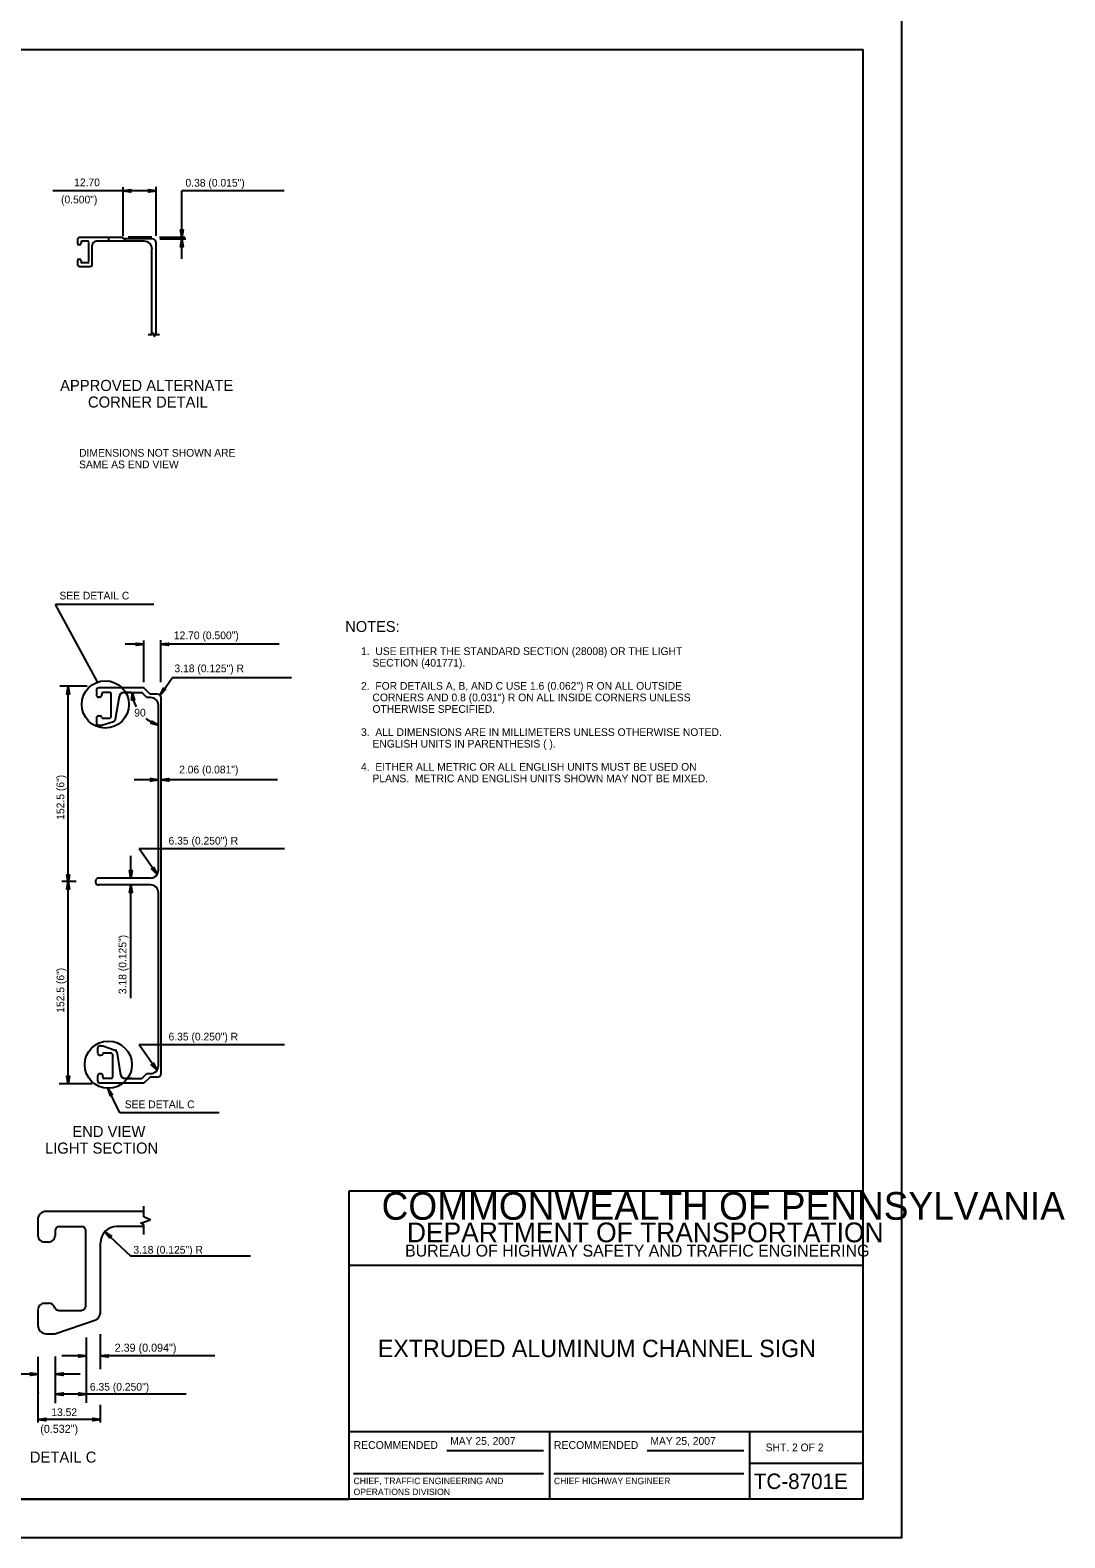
# Model space of a CAD drawing. Extents: x 647822 to 648727, y 298458 to 299646.
# Drawn here: x 648324 to 648727, y 298458 to 299044 of the extents above; entities that cross this region are included whole.
import ezdxf

# ---------------------------------------------------------------- set-up
doc = ezdxf.new("R2010")
doc.units = 0
for name, color, linetype in [('1', 7, 'Continuous'), ('2', 7, 'Continuous'), ('3', 7, 'Continuous'), ('XCS-GRID-MIN', 7, 'Continuous')]:
    doc.layers.add(name, color=color, linetype=linetype)

# ---------------------------------------------------------------- blocks, each defined once
blk = doc.blocks.new('RARROW')
at = {"layer": '3'}
blk.add_lwpolyline([(-2.2695, 0.285), (-2.184875, 0.12075), (0, 0), (-2.2695, 0.285), (-2.38575, 0.384625), (0, 0), (-2.183125, -0.108), (-2.262875, -0.2705), (0, 0), (-2.38575, -0.379125), (-2.262875, -0.2705)], dxfattribs=at)

msp = doc.modelspace()

# ---------------------------------------------------------------- linework, layer by layer
at = {"layer": '1'}
for p, q in [((647862.31, 299036.63), (648648.31, 299036.63)), ((648648.31, 298472.63), (648648.31, 299036.63)), ((648448.31, 298472.63), (648448.31, 298592.63)), ((648448.31, 298592.63), (648648.31, 298592.63)), ((648648.31, 298563.63), (648448.31, 298563.63)), ((648448.31, 298499), (648648.31, 298499)), ((648526.31, 298499), (648526.31, 298472.63)), ((648604.19, 298472.63), (648604.19, 298499)), ((648486.24, 298491.57), (648523.87, 298491.57)), ((648564.24, 298491.57), (648601.87, 298491.57)), ((648449.99, 298482.68), (648523.87, 298482.68)), ((648527.99, 298482.68), (648601.87, 298482.68)), ((648604.19, 298486.63), (648648.31, 298486.63)), ((648648.31, 298472.63), (647862.31, 298472.63)), ((647862.31, 298472.63), (648448.31, 298472.63))]:
    msp.add_line(p, q, dxfattribs=at)
at = {"layer": '2'}
for p, q in [((648373.15, 298981.61), (648332.95, 298981.61)), ((648360.27, 298964.08), (648360.27, 298982.99)), ((648373.15, 298964.08), (648373.15, 298983.24)), ((648422.96, 298981.61), (648383.15, 298981.61)), ((648383.15, 298963.45), (648383.15, 298981.61)), ((648342.52, 298962.58), (648342.52, 298961.2)), ((648360.27, 298963.45), (648343.27, 298963.45)), ((648354.65, 298963.45), (648354.65, 298962.08)), ((648360.27, 298962.95), (648360.27, 298963.45)), ((648371.65, 298962.95), (648360.27, 298962.95)), ((648361.02, 298962.08), (648361.02, 298962.95)), ((648371.52, 298963.58), (648362.27, 298963.58)), ((648384.4, 298963.45), (648374.4, 298963.45)), ((648384.65, 298962.83), (648374.52, 298962.83)), ((648383.15, 298955.2), (648383.15, 298962.83)), ((648343.27, 298960.58), (648343.15, 298960.58)), ((648343.9, 298961.58), (648343.9, 298961.2)), ((648346.52, 298962.08), (648344.27, 298962.08)), ((648346.9, 298954.08), (648346.9, 298961.58)), ((648348.27, 298953.08), (648348.27, 298960.45)), ((648368.52, 298962.08), (648349.9, 298962.08)), ((648371.52, 298925.7), (648371.52, 298958.95)), ((648373.15, 298925.7), (648373.15, 298961.45)), ((648342.52, 298954.45), (648342.52, 298953.08)), ((648343.15, 298955.08), (648343.27, 298955.08)), ((648343.27, 298952.2), (648347.52, 298952.2)), ((648343.9, 298954.45), (648343.9, 298954.08)), ((648344.27, 298953.7), (648346.52, 298953.7)), ((648370.02, 298925.7), (648371.77, 298925.7)), ((648372.9, 298925.7), (648374.4, 298925.7)), ((648372.22, 298820.73), (648333.97, 298820.73)), ((648350.25, 298790.63), (648333.97, 298820.73)), ((648368.38, 298805.22), (648361.12, 298805.22)), ((648368.38, 298790.5), (648368.38, 298806.72)), ((648375, 298790.5), (648375, 298806.85)), ((648420.97, 298805.22), (648375, 298805.22)), ((648346.25, 298788.88), (648335.62, 298788.88)), ((648338.88, 298712.5), (648338.88, 298788.88)), ((648349.88, 298787.25), (648349.88, 298785.38)), ((648368.38, 298788.25), (648350.88, 298788.25)), ((648370.75, 298785.88), (648368.38, 298788.25)), ((648374.65, 298785.41), (648379.38, 298792.13)), ((648425.82, 298792.13), (648379.38, 298792.13)), ((648351.25, 298784.63), (648350.62, 298784.63)), ((648352, 298786), (648352, 298785.38)), ((648355.12, 298786.5), (648352.5, 298786.5)), ((648355.62, 298777), (648355.62, 298786)), ((648357.38, 298776.13), (648358.88, 298785)), ((648363.38, 298786.5), (648360.5, 298786.5)), ((648360.62, 298786.5), (648367.62, 298786.5)), ((648369.5, 298784.5), (648367.62, 298786.5)), ((648371, 298784.5), (648369.5, 298784.5)), ((648373.53, 298785.88), (648370.75, 298785.88)), ((648374, 298717.38), (648374, 298781.5)), ((648375.12, 298638.38), (648375.12, 298784.28)), ((648349.88, 298776.63), (648349.88, 298774.75)), ((648350.62, 298777.38), (648351.25, 298777.38)), ((648352, 298773.75), (648356.88, 298775.38)), ((648352.38, 298776.5), (648355.12, 298776.5)), ((648350.88, 298773.75), (648352, 298773.75)), ((648374, 298752.5), (648364.62, 298752.5)), ((648420.35, 298752.5), (648375.12, 298752.5)), ((648363.25, 298714.25), (648363.25, 298722.88)), ((648373.5, 298715.63), (648366.5, 298725.63)), ((648423.15, 298725.63), (648366.5, 298725.63)), ((648342, 298713), (648336.38, 298713)), ((648338.88, 298634.25), (648338.88, 298713)), ((648371, 298711.63), (648350.75, 298711.63)), ((648371, 298714.25), (648350.88, 298714.25)), ((648363.25, 298667.5), (648363.25, 298711.63)), ((648374, 298641.13), (648374, 298708.5)), ((648350.38, 298646.25), (648350.38, 298648)), ((648351.38, 298649), (648352.38, 298649)), ((648352.38, 298649), (648357.25, 298647.38)), ((648352.88, 298646.25), (648355.62, 298646.25)), ((648357.88, 298646.63), (648359.25, 298637.75)), ((648373.38, 298639.5), (648366.5, 298649.38)), ((648423.15, 298649.38), (648366.5, 298649.38)), ((648351.12, 298645.38), (648351.62, 298645.38)), ((648356.12, 298645.75), (648356.12, 298636.88)), ((648348.25, 298634.25), (648335.38, 298634.25)), ((648350.38, 298635.5), (648350.38, 298637.38)), ((648351.62, 298638.13), (648351.12, 298638.13)), ((648368.38, 298634.5), (648351.38, 298634.5)), ((648352.38, 298636.88), (648352.38, 298637.38)), ((648355.62, 298636.25), (648352.88, 298636.25)), ((648363.75, 298636.25), (648361, 298636.25)), ((648361.12, 298636.25), (648367.62, 298636.25)), ((648367.62, 298636.25), (648369.5, 298638.25)), ((648370.75, 298636.88), (648368.38, 298634.5)), ((648369.5, 298638.25), (648371, 298638.25)), ((648373.5, 298636.88), (648370.75, 298636.88)), ((648359, 298623), (648354.38, 298632.5)), ((648397.61, 298623), (648359, 298623)), ((648327.08, 298581.43), (648327.08, 298575.25)), ((648368.21, 298584.63), (648330.28, 298584.63)), ((648368.33, 298582.5), (648368.33, 298586.63)), ((648333.78, 298577.03), (648333.78, 298575.28)), ((648335.34, 298578.75), (648344.13, 298578.75)), ((648345.83, 298547.75), (648345.83, 298577.05)), ((648353.18, 298576.72), (648363.25, 298567.17)), ((648368.33, 298578.75), (648357.86, 298578.75)), ((648368.33, 298575.63), (648368.33, 298579.38)), ((648331.31, 298572.67), (648329.56, 298572.67)), ((648351.46, 298544.88), (648351.46, 298572.35)), ((648409.83, 298567.17), (648363.25, 298567.17)), ((648327.08, 298546.25), (648327.08, 298540.38)), ((648329.46, 298548.88), (648331.33, 298548.88)), ((648335.21, 298546.13), (648344.21, 298546.13)), ((648333.71, 298537), (648349.71, 298542.38)), ((648330.33, 298537), (648333.71, 298537)), ((648346.08, 298510.16), (648346.08, 298535.5)), ((648351.46, 298523.28), (648351.46, 298536.88)), ((648327.21, 298502.53), (648327.21, 298528.04)), ((648333.96, 298510.03), (648333.96, 298528.16)), ((648346.08, 298528.38), (648336.46, 298528.38)), ((648345.71, 298528.38), (648340.5, 298528.38)), ((648395.97, 298528.38), (648351.33, 298528.38)), ((648365.08, 298528.38), (648351.46, 298528.38)), ((648327.21, 298521.29), (648297.29, 298521.29)), ((648343.55, 298521.29), (648333.96, 298521.29)), ((648338.35, 298521.29), (648333.96, 298521.29)), ((648327.21, 298515), (648327.08, 298515)), ((648327.21, 298514.22), (648327.21, 298514.09)), ((648384.77, 298513.52), (648333.96, 298513.52)), ((648351.46, 298502.53), (648351.46, 298509.41)), ((648351.46, 298503.63), (648327.21, 298503.63))]:
    msp.add_line(p, q, dxfattribs=at)
for points in [[(648371.77, 298925.7), (648372.02, 298926.2), (648372.52, 298924.95), (648372.9, 298925.7)], [(648368.33, 298579.38), (648367.21, 298580), (648370.83, 298581.38), (648368.33, 298582.5)]]:
    msp.add_lwpolyline(points, dxfattribs=at)
for centre in [(648353.36, 298781.82), (648354.51, 298641.68)]:
    msp.add_circle(centre, 9.19, dxfattribs=at)
for centre, radius, start, end in [((648343.29, 298962.61), 0.795, 90, 180), ((648371.56, 298961.3), 1.6, 0, 90), ((648343.11, 298961.22), 0.612, 180, 270), ((648343.29, 298961.22), 0.612, 270, 0), ((648344.3, 298961.62), 0.398, 90, 180), ((648346.49, 298961.62), 0.398, 0, 90), ((648349.87, 298960.42), 1.59, 90, 180), ((648368.49, 298958.95), 3.08, 0, 90), ((648343.11, 298954.43), 0.612, 90, 180), ((648343.29, 298953.05), 0.795, 180, 270), ((648343.29, 298954.43), 0.612, 0, 90), ((648344.3, 298954.04), 0.398, 180, 270), ((648346.49, 298954.04), 0.398, 270, 0), ((648347.49, 298953.05), 0.795, 270, 0), ((648375.21, 298786.75), 11.37, 181.27007, 209.92369), ((648371, 298781.5), 3, 0, 90), ((648373.53, 298784.28), 1.6, 0, 90), ((648378.03, 298787.43), 14.21, 231.28314, 253.53268), ((648370.95, 298717.33), 3.08, 270, 0), ((648350.82, 298712.94), 1.31, 91.68468, 272.80637), ((648370.97, 298708.56), 3.08, 0, 90), ((648370.97, 298641.28), 3.08, 270, 0), ((648373.45, 298638.41), 1.6, 270, 0), ((648330.28, 298581.43), 3.2, 90, 180), ((648344.13, 298577.05), 1.7, 0, 90), ((648357.86, 298572.35), 6.4, 90, 180)]:
    msp.add_arc(centre, radius, start, end, dxfattribs=at)
for centre, major_axis, start_param, end_param in [((648350.89, 298787.24), (0, -1.04), 3.141593, 4.712389), ((648350.66, 298785.43), (0, -0.797), 4.712389, 6.283185), ((648351.2, 298785.44), (0, 0.797), 3.141593, 4.712389), ((648352.44, 298785.95), (0, -0.518), 3.141593, 4.712389), ((648355.13, 298785.95), (0, 0.518), 4.712389, 6.283185), ((648360.67, 298784.44), (0, -2.07), 3.141593, 4.712389), ((648350.66, 298776.58), (0, 0.797), 0, 1.570796), ((648351.2, 298776.59), (0, 0.797), 5.030839, 6.283185), ((648352.37, 298777.06), (0, -0.518), 5.099486, 6.283185), ((648355.13, 298777.06), (0, 0.518), 3.141593, 4.712389), ((648356.37, 298776.3), (0, -1.04), 0.462932, 1.480604), ((648350.89, 298774.78), (0, -1.04), 4.712389, 6.283185), ((648351.35, 298648.01), (0, -1.04), 3.141593, 4.712389), ((648351.12, 298646.2), (0, -0.797), 4.712389, 6.283185), ((648351.67, 298646.19), (0, -0.797), 0, 1.252346), ((648352.84, 298645.73), (0, 0.518), 0, 1.183699), ((648355.6, 298645.73), (0, 0.518), 4.712389, 6.283185), ((648356.83, 298646.49), (0, 1.04), 4.802582, 5.820253), ((648351.12, 298637.35), (0, -0.797), 3.141593, 4.712389), ((648351.35, 298635.54), (0, -1.04), 4.712389, 6.283185), ((648351.67, 298637.34), (0, 0.797), 4.712389, 6.283185), ((648352.91, 298636.83), (0, -0.518), 4.712389, 6.283185), ((648355.6, 298636.83), (0, -0.518), 0, 1.570796), ((648361.14, 298638.34), (0, -2.07), 4.712389, 6.283185), ((648335.38, 298577.03), (0, -1.7), 3.141593, 4.712389), ((648329.56, 298575.28), (0, -2.61), 4.712389, 6.283185), ((648331.31, 298575.28), (0, 2.61), 3.141593, 4.712389), ((648329.56, 298546.3), (0, 2.61), 0, 1.570796), ((648331.33, 298546.33), (0, 2.61), 5.030839, 6.283185), ((648335.17, 298547.86), (0, -1.7), 5.099486, 6.283185), ((648344.2, 298547.86), (0, 1.7), 3.141593, 4.712389), ((648330.3, 298540.39), (0, -3.39), 4.712389, 6.283185), ((648348.24, 298545.37), (0, -3.39), 0.462932, 1.480604)]:
    msp.add_ellipse(centre, major_axis=major_axis, ratio=0.943396, start_param=start_param, end_param=end_param, dxfattribs=at)
at = {"layer": 'XCS-GRID-MIN'}
msp.add_lwpolyline([(647822.31, 299051.63), (648663.31, 299051.63), (648663.31, 298457.63), (647822.31, 298457.63)], close=True, dxfattribs=at)

# ---------------------------------------------------------------- block references
at = {"layer": '2'}
for p, xscale, yscale, rotation in [((648360.27, 298981.61), 1.2574347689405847, 1.3092961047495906, 180), ((648383.15, 298962.83), 1.2574347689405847, 1.3092961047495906, 89.99999999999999), ((648383.15, 298963.45), 1.2574347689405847, 1.3092961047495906, -90.00000000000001), ((648375, 298805.22), 1.2574347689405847, 1.3092961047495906, 180), ((648338.88, 298788.88), 1.2574347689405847, 1.3092961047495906, 89.99999999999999), ((648363.84, 298786.5), 1.257434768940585, 1.3092961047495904, 97.46813373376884), ((648374.65, 298785.41), 1.257434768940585, 1.3092961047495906, -124.96513947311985), ((648374, 298773.8), 1.2574347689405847, 1.3092961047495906, -21.75660693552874), ((648375.12, 298752.5), 1.2574347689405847, 1.3092961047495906, 180), ((648363.25, 298714.25), 1.2574347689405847, 1.3092961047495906, -90.00000000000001), ((648373.5, 298715.63), 1.2574347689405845, 1.3092961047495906, -55.40907217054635), ((648338.88, 298713), 1.2574347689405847, 1.3092961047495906, 89.99999999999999), ((648338.88, 298712.5), 1.2574347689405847, 1.3092961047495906, -90.00000000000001), ((648363.25, 298711.63), 1.2574347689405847, 1.3092961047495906, 89.99999999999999), ((648373.38, 298639.5), 1.2574347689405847, 1.3092961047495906, -54.62763997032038), ((648338.88, 298634.25), 1.2574347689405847, 1.3092961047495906, -90.00000000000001), ((648354.38, 298632.5), 1.2574347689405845, 1.3092961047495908, 117.67480303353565), ((648353.18, 298576.72), 1.2574347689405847, 1.3092961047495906, 136.94148309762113), ((648351.46, 298528.38), 1.2574347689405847, 1.3092961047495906, 180), ((648333.96, 298521.29), 1.2574347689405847, 1.3092961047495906, 180), ((648333.96, 298513.52), 1.2574347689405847, 1.3092961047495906, 180), ((648327.21, 298503.63), 1.2574347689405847, 1.3092961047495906, 180)]:
    msp.add_blockref('RARROW', p, dxfattribs=dict(at, xscale=xscale, yscale=yscale, rotation=rotation))
at = {"layer": '2', "xscale": 1.2574347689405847, "yscale": 1.3092961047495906}
for p in [(648373.15, 298981.61), (648368.38, 298805.22), (648374, 298752.5), (648346.08, 298528.38), (648327.21, 298521.29), (648346.08, 298513.52), (648351.46, 298503.63)]:
    msp.add_blockref('RARROW', p, dxfattribs=at)

# ---------------------------------------------------------------- texts
at = {"layer": '1'}
for s, height, p in [('COMMONWEALTH OF PENNSYLVANIA', 10.7828, (648460.9, 298581.36)), ('DEPARTMENT OF TRANSPORTATION', 7.6837, (648470.76, 298572.61)), ('BUREAU OF HIGHWAY SAFETY AND TRAFFIC ENGINEERING', 4.6253, (648470.04, 298567.04)), ('EXTRUDED ALUMINUM CHANNEL SIGN', 6.75, (648459.45, 298527.94)), ('RECOMMENDED', 3.048, (648449.99, 298492.2)), ('RECOMMENDED', 3.048, (648527.99, 298492.2)), ('SHT. 2 OF 2', 3, (648610.4, 298491.31)), ('TC-8701E', 6, (648605.79, 298476.63)), ('OPERATIONS DIVISION', 2.5, (648449.99, 298474.26)), ('CHIEF, TRAFFIC ENGINEERING AND', 2.5, (648449.99, 298478.51)), ('CHIEF HIGHWAY ENGINEER', 2.5, (648527.99, 298478.51))]:
    msp.add_text(s, height=height, dxfattribs=at).set_placement(p)
at = {"layer": '2'}
for s, height, p in [('12.70', 3, (648341.21, 298983.41)), ('0.38 (0.015")', 3, (648384.56, 298983.25)), ('(0.500")', 3, (648336.12, 298976.75)), ('APPROVED ALTERNATE', 4.3, (648335.75, 298903.76)), ('CORNER DETAIL', 4.3, (648346.6, 298897.31)), ('DIMENSIONS NOT SHOWN ARE', 3, (648343.15, 298878.2)), ('SAME AS END VIEW', 3, (648343.15, 298873.7)), ('SEE DETAIL C', 3, (648335.49, 298822.66)), ('12.70 (0.500")', 3, (648380.02, 298807.2)), ('NOTES:', 4.25, (648446.76, 298810.02)), ('1.  USE EITHER THE STANDARD SECTION (28008) OR THE LIGHT', 3, (648452.89, 298801.05)), ('    SECTION (401771).', 3, (648452.89, 298796.55)), ('3.18 (0.125") R', 3, (648380.26, 298794.35)), ('2.  FOR DETAILS A, B, AND C USE 1.6 (0.062") R ON ALL OUTSIDE', 3, (648452.89, 298787.55)), ('    OTHERWISE SPECIFIED.', 3, (648452.89, 298778.55)), ('    CORNERS AND 0.8 (0.031") R ON ALL INSIDE CORNERS UNLESS', 3, (648452.89, 298783.05)), ('90', 3, (648364.62, 298777.13)), ('3.  ALL DIMENSIONS ARE IN MILLIMETERS UNLESS OTHERWISE NOTED.', 3, (648452.89, 298769.55)), ('    ENGLISH UNITS IN PARENTHESIS ( ).', 3, (648452.89, 298765.05)), ('2.06 (0.081")', 3, (648382.1, 298755)), ('4.  EITHER ALL METRIC OR ALL ENGLISH UNITS MUST BE USED ON', 3, (648452.89, 298756.05)), ('    PLANS.  METRIC AND ENGLISH UNITS SHOWN MAY NOT BE MIXED.', 3, (648452.89, 298751.55)), ('6.35 (0.250") R', 3, (648377.97, 298727.32)), ('6.35 (0.250") R', 3, (648377.97, 298651.11)), ('SEE DETAIL C', 3, (648360.92, 298624.77)), ('END VIEW', 4.3, (648340.51, 298613.55)), ('LIGHT SECTION', 4.3, (648329.86, 298607.1)), ('3.18 (0.125") R', 3, (648364.27, 298568.19)), ('2.39 (0.094")', 3.1252, (648357, 298530.03)), ('6.35 (0.250")', 3, (648347.35, 298514.89)), ('13.52', 3, (648332.33, 298505)), ('(0.532")', 3.125, (648328.03, 298498.47)), ('MAY 25, 2007', 3, (648487.6, 298493.81)), ('MAY 25, 2007', 3, (648565.54, 298493.81)), ('DETAIL C', 4.3, (648323.99, 298486.88))]:
    msp.add_text(s, height=height, dxfattribs=at).set_placement(p)
for s, p in [('152.5 (6")', (648337.38, 298736.95)), ('3.18 (0.125")', (648361.54, 298669.13)), ('152.5 (6")', (648337.38, 298661.88))]:
    msp.add_text(s, height=3, rotation=90, dxfattribs=at).set_placement(p)

doc.saveas('drawing.dxf')
